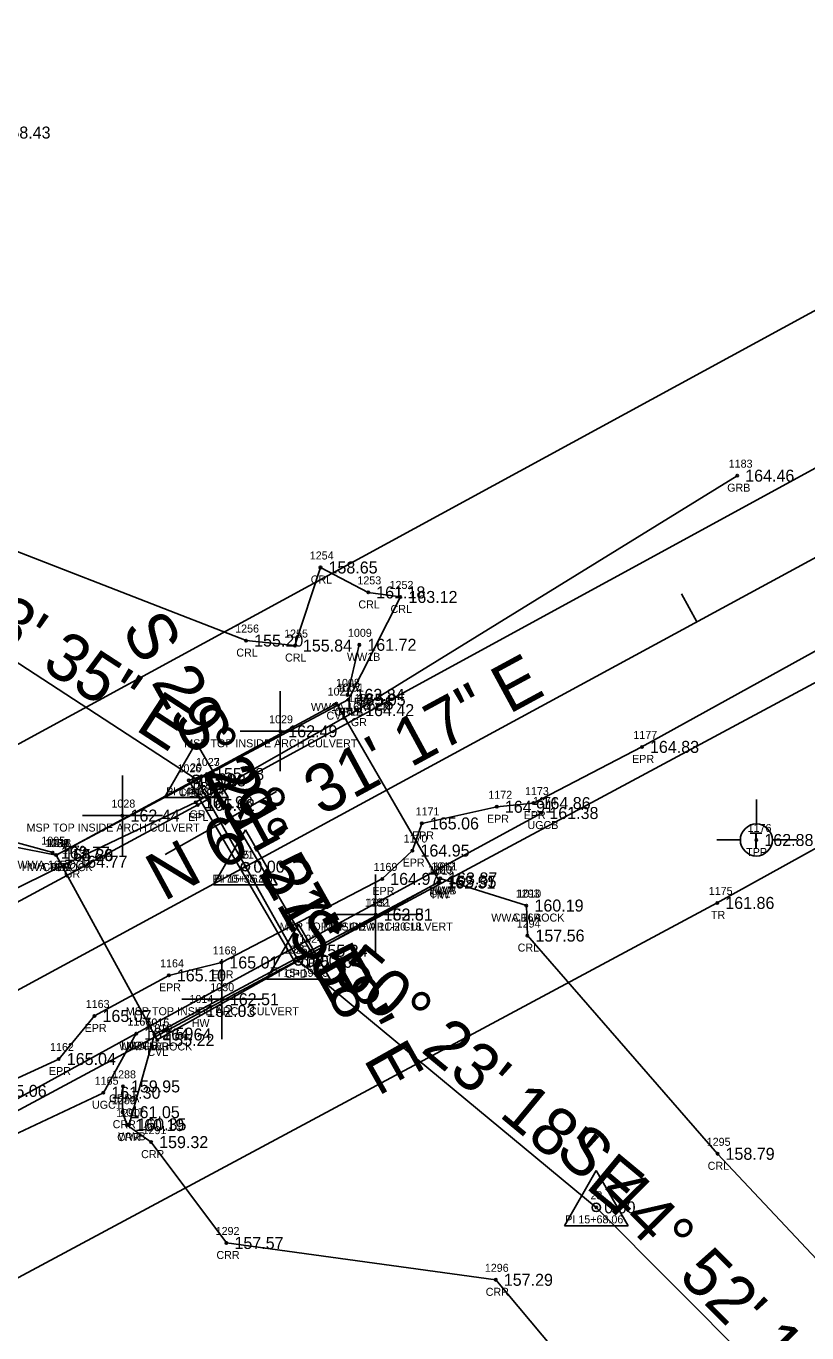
# Model space of a CAD drawing. Extents: x 2279339 to 2281902, y 1061267 to 1062892.
# Drawn here: x 2280207.4 to 2280304.9, y 1061741.1 to 1061904.3 of the extents above; entities that cross this region are included whole.
import ezdxf

# ---------------------------------------------------------------- set-up
doc = ezdxf.new("R2010")
doc.units = 0
for name, color, linetype in [('RD_EX_Bridge', 7, 'Continuous'), ('RD_EX_Bridge_txCode', 7, 'Continuous'), ('RD_EX_Conc', 7, 'Continuous'), ('RD_EX_Conc_txCode', 7, 'Continuous'), ('RD_EX_GuardRail', 7, 'Continuous'), ('RD_EX_GuardRail_txCode', 7, 'Continuous'), ('RD_EX_H2O', 7, 'Continuous'), ('RD_EX_H2O_txCode', 7, 'Continuous'), ('RD_EX_Road', 7, 'Continuous'), ('RD_EX_Road_txCode', 7, 'Continuous'), ('RD_EX_TX_Bridge_ELEV', 7, 'Continuous'), ('RD_EX_TX_Conc_ELEV', 7, 'Continuous'), ('RD_EX_TX_GuardRail_ELEV', 7, 'Continuous'), ('RD_EX_TX_H2O_ELEV', 7, 'Continuous'), ('RD_EX_TX_Misc_ELEV', 7, 'Continuous'), ('RD_EX_TX_Road_ELEV', 7, 'Continuous'), ('RD_EX_TX_UT_ELEV', 7, 'Continuous'), ('RD_EX_TX_VEG_ELEV', 7, 'Continuous'), ('RD_EX_UT', 7, 'Continuous'), ('RD_EX_UT_txCode', 7, 'Continuous'), ('RD_EX_VEG', 7, 'Continuous'), ('RD_EX_VEG_txCode', 7, 'Continuous'), ('RD_HC_Cl', 7, 'Continuous'), ('RD_HC_Data', 7, 'Continuous'), ('RD_HC_Data_Tic', 7, 'Continuous'), ('RD_HC_Survey_ELEV', 7, 'Continuous'), ('RD_HC_txCode', 7, 'Continuous'), ('RD_SMD_Locator', 7, 'Continuous')]:
    doc.layers.add(name, color=color, linetype=linetype)

msp = doc.modelspace()

# ---------------------------------------------------------------- linework, layer by layer
at = {"layer": 'RD_EX_Bridge'}
for p, q in [((2280247.54, 1061820.81), (2280249.02, 1061827.06)), ((2280239.14, 1061811.26), (2280239.14, 1061821.26)), ((2280211.16, 1061800.79), (2280247.67, 1061820.22)), ((2280234.14, 1061816.26), (2280244.14, 1061816.26)), ((2280219.43, 1061800.73), (2280219.43, 1061810.73)), ((2280214.43, 1061805.73), (2280224.43, 1061805.73)), ((2280210.72, 1061801.1), (2280200.05, 1061804.04)), ((2280251.06, 1061788.37), (2280251.06, 1061798.37)), ((2280269.9, 1061794.49), (2280259.12, 1061797.88)), ((2280246.06, 1061793.37), (2280256.06, 1061793.37)), ((2280231.84, 1061777.79), (2280231.84, 1061787.79)), ((2280226.84, 1061782.79), (2280236.84, 1061782.79)), ((2280223.41, 1061778.39), (2280220.28, 1061767.16))]:
    msp.add_line(p, q, dxfattribs=at)
for points in [[(2280211.14, 1061800.8), (2280223.78, 1061777.7), (2280259.02, 1061797.49), (2280246.16, 1061819.72), (2280211.14, 1061800.8)], [(2280259.12, 1061797.88), (2280258.89, 1061797.37), (2280228.9, 1061781.32), (2280223.41, 1061778.39)]]:
    msp.add_lwpolyline(points, dxfattribs=at)
for centre in [(2280239.14, 1061816.26), (2280219.43, 1061805.73), (2280251.06, 1061793.37), (2280231.84, 1061782.79)]:
    msp.add_circle(centre, 0.15, dxfattribs=at)
at = {"layer": 'RD_EX_Conc'}
msp.add_lwpolyline([(2280229.99, 1061810.92), (2280242.91, 1061788.85), (2280240.97, 1061787.47), (2280227.71, 1061810.13), (2280229.99, 1061810.92)], dxfattribs=at)
at = {"layer": 'RD_EX_GuardRail'}
msp.add_line((2280174.08, 1061751.56), (2280309.28, 1061824.13), dxfattribs=at)
msp.add_lwpolyline([(2280161.35, 1061774.54), (2280212.91, 1061799.96), (2280228.59, 1061807.39), (2280248.74, 1061818.9), (2280296.23, 1061848.19)], dxfattribs=at)
at = {"layer": 'RD_EX_H2O'}
for p, q in [((2280251.06, 1061788.37), (2280251.06, 1061798.37)), ((2280246.06, 1061793.37), (2280256.06, 1061793.37))]:
    msp.add_line(p, q, dxfattribs=at)
for points in [[(2280211.16, 1061800.79), (2280200.18, 1061802.95), (2280195.55, 1061801.16), (2280185.62, 1061809.36), (2280166.4, 1061839.27), (2280165.19, 1061847.77), (2280176.13, 1061895.97), (2280173.38, 1061913.11), (2280146.96, 1061940.88), (2280090.97, 1061964.76), (2280049.27, 1062002.4), (2280058.65, 1062048.88), (2280050.78, 1062064.28), (2280035.9, 1062083.09), (2280001.73, 1062095.49), (2279975.65, 1062129.45), (2279976.82, 1062173.44)], [(2280247.67, 1061820.22), (2280254.15, 1061833.04), (2280250.13, 1061833.61), (2280244.17, 1061836.72), (2280240.97, 1061826.97), (2280234.88, 1061827.59), (2280194.99, 1061843.09), (2280190.85, 1061845.93), (2280191.54, 1061875.47), (2280203.31, 1061891.05), (2280202.74, 1061912.57), (2280161.92, 1061962.77), (2280106.66, 1061987.64), (2280081.48, 1062000.69), (2280077.59, 1062019.21), (2280091.23, 1062055.4), (2280068.77, 1062094.03), (2280025.87, 1062122.57), (2280008.58, 1062126.75), (2280003.39, 1062153.96)], [(2280269.9, 1061794.49), (2280270.02, 1061790.74), (2280293.77, 1061763.48), (2280320.49, 1061735.05), (2280335.4, 1061680.01), (2280309.48, 1061674.63), (2280300.03, 1061660.41), (2280304.47, 1061633.12), (2280315.65, 1061587.64), (2280305.89, 1061543.57), (2280270.77, 1061524.54), (2280257.61, 1061536.28), (2280249.22, 1061535.26), (2280269.33, 1061502.83), (2280301.34, 1061480.02), (2280355.94, 1061475.37), (2280377.91, 1061459.94), (2280379.03, 1061433), (2280360.13, 1061417.18), (2280333.79, 1061387.95)], [(2280219.49, 1061771.9), (2280219.45, 1061768.68), (2280220.02, 1061767.07), (2280223.01, 1061764.94), (2280232.42, 1061752.34), (2280266.07, 1061747.74), (2280284.73, 1061725.48), (2280294.86, 1061698.39), (2280278.35, 1061688.54), (2280267.33, 1061659.35), (2280270.69, 1061629.09), (2280284.25, 1061605.42), (2280287.8, 1061578.54), (2280274.54, 1061562.25), (2280261.24, 1061561.71), (2280231.85, 1061561.45), (2280221.24, 1061537.21), (2280230.8, 1061514.2), (2280261.74, 1061476.46), (2280301.47, 1061455.38), (2280325.75, 1061454.26), (2280345.44, 1061445.29), (2280345.67, 1061436.49), (2280313.46, 1061411.55)]]:
    msp.add_lwpolyline(points, dxfattribs=at)
msp.add_circle((2280251.06, 1061793.37), 0.15, dxfattribs=at)
at = {"layer": 'RD_EX_Road'}
for points in [[(2279554.31, 1061441.46), (2279636.61, 1061486.51), (2279673.46, 1061506.76), (2279683.06, 1061512.21), (2279723.14, 1061533.54), (2279809.28, 1061580.29), (2279896.91, 1061627.91), (2279977.07, 1061671.02), (2280059.64, 1061715.57), (2280142.91, 1061760.72), (2280228.83, 1061807.06), (2280306.04, 1061849.18), (2280392.98, 1061896.71), (2280482.82, 1061945.75), (2280567.83, 1061991.78), (2280649.94, 1062036.55), (2280660.56, 1062042.19), (2280676.12, 1062050.66), (2280737.28, 1062083.64), (2280828.54, 1062132.77), (2280887.86, 1062164.61), (2280934.91, 1062190.9)], [(2279906, 1061609.76), (2279987.33, 1061653.65), (2280069.09, 1061697.76), (2280153.19, 1061743.35), (2280194.51, 1061765.35), (2280202.82, 1061771.34), (2280211.47, 1061775.32), (2280215.93, 1061780.7), (2280225.22, 1061785.77), (2280231.78, 1061787.38), (2280251.88, 1061797.82), (2280255.66, 1061801.36), (2280256.83, 1061804.75), (2280266.2, 1061806.83), (2280270.78, 1061807.29), (2280284.33, 1061814.31), (2280315.09, 1061831.32), (2280403.05, 1061879.04)]]:
    msp.add_lwpolyline(points, dxfattribs=at)
at = {"layer": 'RD_EX_UT'}
for p, q in [((2280298.62, 1061807.75), (2280298.62, 1061804.68)), ((2280293.69, 1061802.7), (2280296.62, 1061802.7)), ((2280300.62, 1061802.7), (2280303.69, 1061802.7))]:
    msp.add_line(p, q, dxfattribs=at)
for points in [[(2280196.99, 1061765.27), (2280221.15, 1061778.49), (2280271.76, 1061806.05)], [(2280197.2, 1061761.76), (2280217.04, 1061771.11), (2280221.15, 1061778.49)]]:
    msp.add_lwpolyline(points, dxfattribs=at)
msp.add_circle((2280298.62, 1061802.68), 2, dxfattribs=at)
at = {"layer": 'RD_EX_VEG'}
for points in [[(2279558.89, 1061483.89), (2279567.79, 1061465.98), (2279895.37, 1061645.37), (2280383.77, 1061911.19), (2280927.05, 1062203.11)], [(2279742.03, 1061456.73), (2279738.34, 1061498.5), (2279914.03, 1061591.25), (2280293.74, 1061794.82), (2280950.97, 1062158.54)]]:
    msp.add_lwpolyline(points, dxfattribs=at)
at = {"layer": 'RD_HC_Cl'}
for p, q in [((2279559.77, 1061433.17), (2280939.55, 1062181.67)), ((2280176.21, 1061844.46), (2280228.65, 1061810.26)), ((2280228.65, 1061810.26), (2280234.79, 1061799.35)), ((2280234.79, 1061799.35), (2280241.4, 1061787.59)), ((2280241.4, 1061787.59), (2280278.62, 1061756.79)), ((2280278.62, 1061756.79), (2280304.92, 1061730.37))]:
    msp.add_line(p, q, dxfattribs=at)
at = {"layer": 'RD_HC_Data'}
for p, q in [((2280224.68, 1061807.97), (2280228.65, 1061814.85)), ((2280228.65, 1061814.85), (2280232.62, 1061807.97)), ((2280224.68, 1061807.97), (2280232.62, 1061807.97)), ((2280230.82, 1061797.06), (2280234.79, 1061803.94)), ((2280230.82, 1061797.06), (2280234.79, 1061803.94)), ((2280234.79, 1061803.94), (2280238.76, 1061797.06)), ((2280234.79, 1061803.94), (2280238.76, 1061797.06)), ((2280230.82, 1061797.06), (2280238.76, 1061797.06)), ((2280230.82, 1061797.06), (2280238.76, 1061797.06)), ((2280237.43, 1061785.3), (2280241.4, 1061792.18)), ((2280241.4, 1061792.18), (2280245.37, 1061785.3)), ((2280237.43, 1061785.3), (2280245.37, 1061785.3)), ((2280274.65, 1061754.5), (2280278.62, 1061761.38)), ((2280278.62, 1061761.38), (2280282.59, 1061754.5)), ((2280274.65, 1061754.5), (2280282.59, 1061754.5))]:
    msp.add_line(p, q, dxfattribs=at)
for centre in [(2280228.65, 1061810.26), (2280234.79, 1061799.35), (2280234.79, 1061799.35), (2280241.4, 1061787.59), (2280278.62, 1061756.79)]:
    msp.add_circle(centre, 0.529, dxfattribs=at)
at = {"layer": 'RD_HC_Data_Tic'}
for p, q in [((2280291.18, 1061829.94), (2280289.27, 1061833.45)), ((2280231.72, 1061804.8), (2280238.69, 1061808.73)), ((2280231.72, 1061804.8), (2280224.75, 1061800.88))]:
    msp.add_line(p, q, dxfattribs=at)
at = {"layer": 'RD_SMD_Locator'}
for centre in [(2280296.23, 1061848.19), (2280244.17, 1061836.72), (2280250.13, 1061833.61), (2280254.15, 1061833.04), (2280234.88, 1061827.59), (2280240.97, 1061826.97), (2280249.02, 1061827.06), (2280247.54, 1061820.81), (2280247.67, 1061820.22), (2280247.67, 1061820.22), (2280246.16, 1061819.72), (2280248.74, 1061818.9), (2280284.33, 1061814.31), (2280229.99, 1061810.92), (2280229.99, 1061810.92), (2280227.71, 1061810.13), (2280228.65, 1061810.26), (2280228.59, 1061807.39), (2280270.78, 1061807.29), (2280228.83, 1061807.06), (2280266.2, 1061806.83), (2280271.76, 1061806.05), (2280256.83, 1061804.75), (2280298.62, 1061802.68), (2280210.72, 1061801.1), (2280211.14, 1061800.8), (2280211.14, 1061800.8), (2280211.16, 1061800.79), (2280211.16, 1061800.79), (2280255.66, 1061801.36), (2280212.91, 1061799.96), (2280234.79, 1061799.35), (2280234.79, 1061799.35), (2280251.88, 1061797.82), (2280258.89, 1061797.37), (2280259.02, 1061797.49), (2280259.12, 1061797.88), (2280259.12, 1061797.88), (2280269.9, 1061794.49), (2280269.9, 1061794.49), (2280293.74, 1061794.82), (2280270.02, 1061790.74), (2280241.4, 1061787.59), (2280242.91, 1061788.85), (2280231.78, 1061787.38), (2280240.97, 1061787.47), (2280225.22, 1061785.77), (2280228.9, 1061781.32), (2280215.93, 1061780.7), (2280221.15, 1061778.49), (2280221.15, 1061778.49), (2280223.41, 1061778.39), (2280223.41, 1061778.39), (2280223.78, 1061777.7), (2280211.47, 1061775.32), (2280219.49, 1061771.9), (2280217.04, 1061771.11), (2280219.45, 1061768.68), (2280220.02, 1061767.07), (2280220.28, 1061767.16), (2280223.01, 1061764.94), (2280293.77, 1061763.48), (2280278.62, 1061756.79), (2280232.42, 1061752.34), (2280266.07, 1061747.74)]:
    msp.add_circle(centre, 0.15, dxfattribs=at)

# ---------------------------------------------------------------- texts
at = {"layer": 'RD_EX_Bridge_txCode'}
for s, p in [('1009', (2280247.6, 1061828.06)), ('WW1B', (2280247.48, 1061825.06)), ('1008', (2280246.11, 1061821.81)), ('1007', (2280246.24, 1061821.22)), ('1021', (2280245.06, 1061820.72)), ('WW1A 16ROCK', (2280242.97, 1061818.81)), ('CVL', (2280244.92, 1061817.72)), ('HWB', (2280246.38, 1061818.22)), ('1029', (2280237.75, 1061817.26)), ('MSP TOP INSIDE ARCH CULVERT', (2280227.15, 1061814.26)), ('1028', (2280218.05, 1061806.73)), ('MSP TOP INSIDE ARCH CULVERT', (2280207.45, 1061803.73)), ('1005', (2280209.29, 1061802.1)), ('1004', (2280209.74, 1061801.79)), ('1022', (2280209.75, 1061801.8)), ('1018', (2280210.04, 1061801.8)), ('WWA 16ROCK', (2280206.32, 1061799.1)), ('HWA 16ROCK', (2280206.85, 1061798.79)), ('CVLA', (2280209.41, 1061798.8)), ('CVLB', (2280209.42, 1061798.8)), ('1020', (2280257.6, 1061798.49)), ('1013', (2280257.79, 1061798.37)), ('1012', (2280258.02, 1061798.88)), ('1011', (2280258.3, 1061798.88)), ('WWB', (2280257.74, 1061795.88)), ('CVL', (2280257.78, 1061795.49)), ('HWA', (2280257.82, 1061795.88)), ('HW', (2280258.07, 1061795.37)), ('1010', (2280268.76, 1061795.49)), ('1031', (2280249.96, 1061794.37)), ('WWA 16ROCK', (2280265.5, 1061792.49)), ('MSP TOP INSIDE ARCH CULVERT', (2280239.07, 1061791.37)), ('1030', (2280230.41, 1061783.79)), ('1014', (2280227.8, 1061782.32)), ('MSP TOP INSIDE ARCH CULVERT', (2280219.85, 1061780.79)), ('1016', (2280222.29, 1061779.39)), ('1015', (2280222.31, 1061779.39)), ('1019', (2280222.68, 1061778.7)), ('HW', (2280228.08, 1061779.32)), ('WWA 16ROCK', (2280219.01, 1061776.39)), ('HWB', (2280222.12, 1061776.39)), ('CVL', (2280222.54, 1061775.7)), ('1017', (2280219.17, 1061768.16)), ('WWB', (2280218.9, 1061765.16))]:
    msp.add_text(s, height=1, dxfattribs=at).set_placement(p)
at = {"layer": 'RD_EX_Conc_txCode'}
for s, p in [('1023', (2280228.6, 1061811.92)), ('1027', (2280228.6, 1061811.92)), ('1026', (2280226.3, 1061811.13)), ('CPD', (2280226.46, 1061808.13)), ('CPDA', (2280228.25, 1061808.92)), ('CPDB', (2280228.27, 1061808.92)), ('1025', (2280239.58, 1061788.47)), ('1024', (2280241.52, 1061789.85)), ('CPD', (2280241.66, 1061786.85)), ('CPD', (2280239.71, 1061785.47))]:
    msp.add_text(s, height=1, dxfattribs=at).set_placement(p)
at = {"layer": 'RD_EX_GuardRail_txCode'}
for s, p in [('1183', (2280295.17, 1061849.19)), ('GRB', (2280294.98, 1061846.19)), ('1182', (2280247.67, 1061819.9)), ('GR', (2280247.96, 1061816.9)), ('1181', (2280227.81, 1061808.39)), ('GR', (2280227.81, 1061805.39)), ('1179', (2280211.85, 1061800.96)), ('GR', (2280212.14, 1061797.96))]:
    msp.add_text(s, height=1, dxfattribs=at).set_placement(p)
at = {"layer": 'RD_EX_H2O_txCode'}
for s, p in [('1254', (2280242.83, 1061837.72)), ('CRL', (2280242.95, 1061834.72)), ('1253', (2280248.78, 1061834.61)), ('1252', (2280252.8, 1061834.04)), ('CRL', (2280248.9, 1061831.61)), ('CRL', (2280252.92, 1061831.04)), ('1256', (2280233.51, 1061828.59)), ('1255', (2280239.63, 1061827.97)), ('CRL', (2280233.65, 1061825.59)), ('CRL', (2280239.74, 1061824.97)), ('1251', (2280246.6, 1061821.22)), ('CRLA', (2280245.95, 1061818.22)), ('1258', (2280209.82, 1061801.79)), ('CRRA', (2280209.42, 1061798.79)), ('1293', (2280268.56, 1061795.49)), ('1332', (2280249.71, 1061794.37)), ('CRLA', (2280268.18, 1061792.49)), ('1294', (2280268.68, 1061791.74)), ('MSP ODW 11-20-18', (2280244.54, 1061791.37)), ('CRL', (2280268.8, 1061788.74)), ('1288', (2280218.14, 1061772.9)), ('CRRA', (2280217.75, 1061769.9)), ('1289', (2280218.11, 1061769.68)), ('1290', (2280218.64, 1061768.07)), ('CRR', (2280218.2, 1061766.68)), ('1291', (2280221.94, 1061765.94)), ('CRR', (2280218.77, 1061765.07)), ('1295', (2280292.42, 1061764.48)), ('CRR', (2280221.76, 1061762.94)), ('CRL', (2280292.54, 1061761.48)), ('1292', (2280231.07, 1061753.34)), ('CRR', (2280231.17, 1061750.34)), ('1296', (2280264.7, 1061748.74)), ('CRR', (2280264.81, 1061745.74))]:
    msp.add_text(s, height=1, dxfattribs=at).set_placement(p)
at = {"layer": 'RD_EX_Road_txCode'}
for s, p in [('1177', (2280283.26, 1061815.31)), ('EPR', (2280283.1, 1061812.31)), ('1180', (2280227.72, 1061808.06)), ('1173', (2280269.72, 1061808.29)), ('1172', (2280265.14, 1061807.83)), ('EPL', (2280227.62, 1061805.06)), ('1171', (2280256.05, 1061805.75)), ('EPR', (2280264.97, 1061804.83)), ('EPR', (2280269.55, 1061805.29)), ('1170', (2280254.55, 1061802.36)), ('EPR', (2280255.6, 1061802.75)), ('1169', (2280250.8, 1061798.82)), ('EPR', (2280254.43, 1061799.36)), ('EPR', (2280250.66, 1061795.82)), ('1168', (2280230.7, 1061788.38)), ('1164', (2280224.13, 1061786.77)), ('EPR', (2280230.55, 1061785.38)), ('EPR', (2280223.99, 1061783.77)), ('1163', (2280214.84, 1061781.7)), ('EPR', (2280214.7, 1061778.7)), ('1162', (2280210.38, 1061776.32)), ('EPR', (2280210.24, 1061773.32))]:
    msp.add_text(s, height=1, dxfattribs=at).set_placement(p)
at = {"layer": 'RD_EX_TX_Bridge_ELEV'}
for s, p in [('161.72', (2280250.02, 1061826.31)), ('155.25', (2280247.16, 1061818.97)), ('163.84', (2280248.54, 1061820.06)), ('165.05', (2280248.67, 1061819.47)), ('163.77', (2280211.72, 1061800.35)), ('155.29', (2280212.14, 1061800.05)), ('155.29', (2280212.14, 1061800.05)), ('164.86', (2280212.16, 1061800.04)), ('162.51', (2280259.89, 1061796.62)), ('155.35', (2280260.02, 1061796.74)), ('163.87', (2280260.12, 1061797.13)), ('163.87', (2280260.12, 1061797.13)), ('160.19', (2280270.9, 1061793.74)), ('162.03', (2280229.9, 1061780.57)), ('164.64', (2280224.41, 1061777.64)), ('164.64', (2280224.41, 1061777.64)), ('155.22', (2280224.78, 1061776.95)), ('160.35', (2280221.28, 1061766.41))]:
    msp.add_text(s, height=1.5, dxfattribs=at).set_placement(p)
at = {"layer": 'RD_EX_TX_Conc_ELEV'}
for s, p in [('155.28', (2280228.71, 1061809.38)), ('155.38', (2280230.99, 1061810.17)), ('155.38', (2280230.99, 1061810.17)), ('155.24', (2280243.91, 1061788.1)), ('155.26', (2280241.97, 1061786.72))]:
    msp.add_text(s, height=1.5, dxfattribs=at).set_placement(p)
at = {"layer": 'RD_EX_TX_GuardRail_ELEV'}
for s, p in [('164.46', (2280297.23, 1061847.44)), ('164.42', (2280249.74, 1061818.15)), ('164.98', (2280229.59, 1061806.64)), ('164.77', (2280213.91, 1061799.21))]:
    msp.add_text(s, height=1.5, dxfattribs=at).set_placement(p)
at = {"layer": 'RD_EX_TX_H2O_ELEV'}
for s, p in [('158.43', (2280204.31, 1061890.3)), ('158.65', (2280245.17, 1061835.97)), ('161.18', (2280251.13, 1061832.86)), ('163.12', (2280255.15, 1061832.29)), ('155.20', (2280235.88, 1061826.84)), ('155.84', (2280241.97, 1061826.22)), ('165.05', (2280248.67, 1061819.47)), ('164.86', (2280212.16, 1061800.04)), ('160.19', (2280270.9, 1061793.74)), ('157.56', (2280271.02, 1061789.99)), ('159.95', (2280220.49, 1061771.15)), ('161.05', (2280220.45, 1061767.93)), ('160.19', (2280221.02, 1061766.32)), ('159.32', (2280224.01, 1061764.19)), ('158.79', (2280294.77, 1061762.73)), ('157.57', (2280233.42, 1061751.59)), ('157.29', (2280267.07, 1061746.99))]:
    msp.add_text(s, height=1.5, dxfattribs=at).set_placement(p)
at = {"layer": 'RD_EX_TX_Misc_ELEV'}
for s, p in [('162.49', (2280240.14, 1061815.51)), ('162.44', (2280220.43, 1061804.98)), ('162.51', (2280252.06, 1061792.62)), ('153.81', (2280252.06, 1061792.62)), ('162.51', (2280232.84, 1061782.04))]:
    msp.add_text(s, height=1.5, dxfattribs=at).set_placement(p)
at = {"layer": 'RD_EX_TX_Road_ELEV'}
for s, p in [('164.83', (2280285.33, 1061813.56)), ('165.02', (2280229.83, 1061806.31)), ('164.91', (2280267.2, 1061806.08)), ('164.86', (2280271.78, 1061806.54)), ('165.06', (2280257.83, 1061804)), ('164.95', (2280256.66, 1061800.61)), ('164.97', (2280252.88, 1061797.07)), ('165.01', (2280232.78, 1061786.63)), ('165.10', (2280226.22, 1061785.02)), ('165.07', (2280216.93, 1061779.95)), ('165.04', (2280212.47, 1061774.57)), ('165.06', (2280203.82, 1061770.59))]:
    msp.add_text(s, height=1.5, dxfattribs=at).set_placement(p)
at = {"layer": 'RD_EX_TX_UT_ELEV'}
for s, p in [('161.38', (2280272.76, 1061805.3)), ('162.88', (2280299.62, 1061801.93)), ('162.59', (2280222.15, 1061777.74)), ('162.59', (2280222.15, 1061777.74)), ('161.30', (2280218.04, 1061770.36))]:
    msp.add_text(s, height=1.5, dxfattribs=at).set_placement(p)
at = {"layer": 'RD_EX_TX_VEG_ELEV'}
msp.add_text('161.86', height=1.5, dxfattribs=at).set_placement((2280294.74, 1061794.07))
at = {"layer": 'RD_EX_UT'}
msp.add_text('T', height=2, dxfattribs=at).set_placement((2280297.77, 1061801.64))
at = {"layer": 'RD_EX_UT_txCode'}
for s, p in [('1174', (2280270.7, 1061807.05)), ('UGCB', (2280270.03, 1061804.05)), ('1176', (2280297.53, 1061803.68)), ('TPP', (2280297.35, 1061800.68)), ('1166', (2280220.04, 1061779.49)), ('1167', (2280220.06, 1061779.49)), ('UGC1B', (2280219.25, 1061776.49)), ('UGC', (2280219.89, 1061776.49)), ('1165', (2280215.96, 1061772.11)), ('UGC1', (2280215.62, 1061769.11))]:
    msp.add_text(s, height=1, dxfattribs=at).set_placement(p)
at = {"layer": 'RD_EX_VEG_txCode'}
for s, p in [('1175', (2280292.68, 1061795.82)), ('TR', (2280292.95, 1061792.82))]:
    msp.add_text(s, height=1, dxfattribs=at).set_placement(p)
at = {"layer": 'RD_HC_Data'}
for s, rotation, p in [('S 56%%d 53\' 35" E', 326.893, (2280180.15, 1061843.08)), ('S 29%%d 21\' 57" E', 299.3657, (2280219.23, 1061829.04)), ('N 61%%d 31\' 17" E', 28.4787, (2280224.59, 1061794.95)), ('S 29%%d 21\' 58" E', 299.3661, (2280225.61, 1061817.7)), ('S 50%%d 23\' 18" E', 320.3883, (2280239.66, 1061790.33)), ('S 44%%d 52\' 11" E', 314.8698, (2280273.26, 1061763.6))]:
    msp.add_text(s, height=6, rotation=rotation, dxfattribs=at).set_placement(p)
at = {"layer": 'RD_HC_Survey_ELEV'}
for p in [(2280229.65, 1061809.51), (2280235.79, 1061798.6), (2280235.79, 1061798.6), (2280242.4, 1061786.84), (2280279.62, 1061756.04)]:
    msp.add_text('0.00', height=1.5, dxfattribs=at).set_placement(p)
at = {"layer": 'RD_HC_txCode'}
for s, p in [('20', (2280227.87, 1061811.26)), ('PI 14+93.74', (2280224.87, 1061808.26)), ('21', (2280234.34, 1061800.35)), ('5', (2280234.5, 1061800.35)), ('PI 70+35.85', (2280230.68, 1061797.35)), ('PI 15+06.26', (2280230.92, 1061797.35)), ('22', (2280240.67, 1061788.59)), ('PI 15+19.75', (2280237.91, 1061785.59)), ('23', (2280277.89, 1061757.79)), ('PI 15+68.06', (2280274.75, 1061754.79))]:
    msp.add_text(s, height=1, dxfattribs=at).set_placement(p)

doc.saveas('drawing.dxf')
